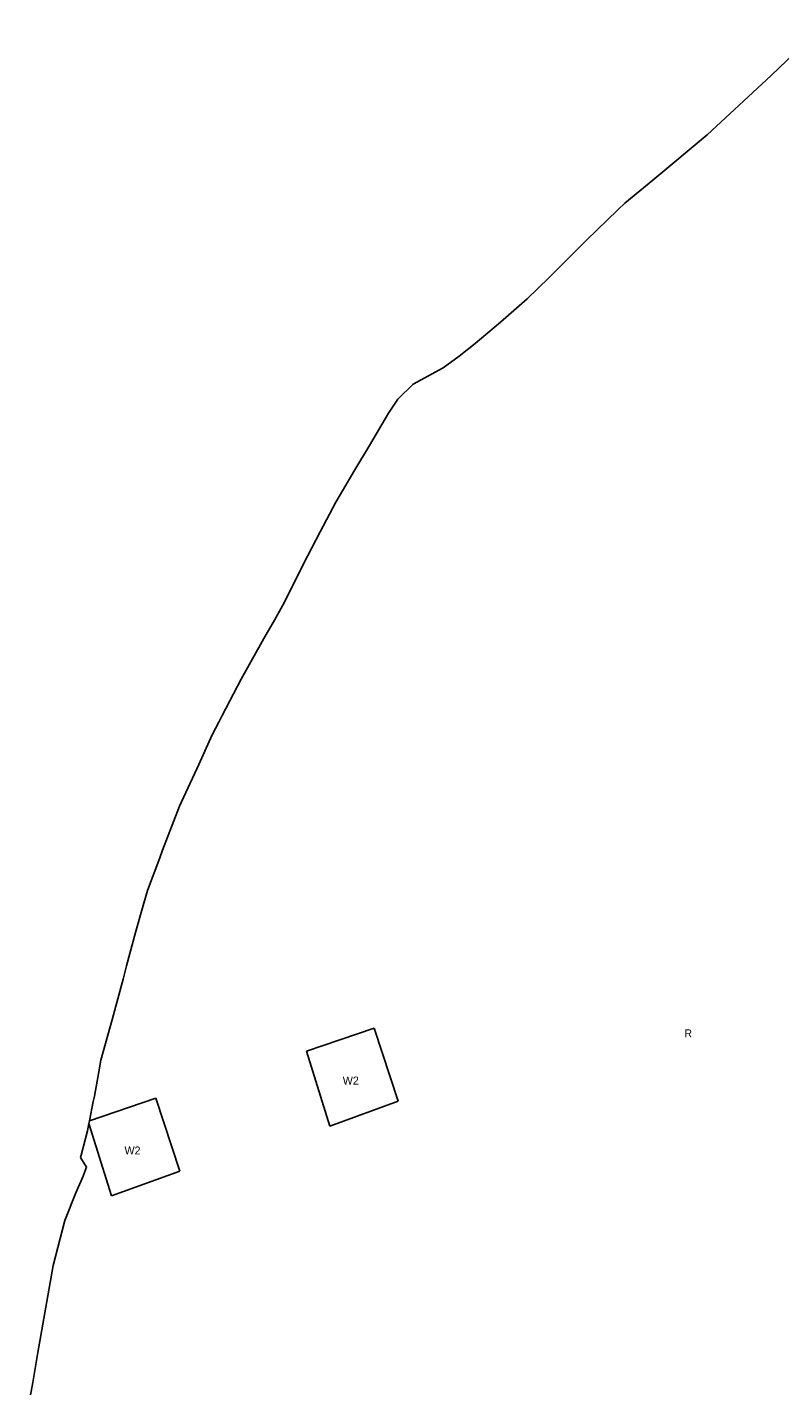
# Model space of a CAD drawing. Extents: x 7435758 to 7439981, y 5550649 to 5554049.
# Drawn here: x 7438745 to 7439233, y 5552845 to 5553728 of the extents above; entities that cross this region are included whole.
import ezdxf

# ---------------------------------------------------------------- set-up
doc = ezdxf.new("R2010")
doc.units = 0
doc.layers.add('linie_rozgraniczające', color=7, linetype='Continuous')
doc.layers.add('oznaczenia_przeznaczen', color=7, linetype='Continuous')

msp = doc.modelspace()

# ---------------------------------------------------------------- linework, layer by layer
at = {"layer": 'linie_rozgraniczające'}
for p, q in [((7439227.86, 5553696.6), (7439260.4, 5553728.02)), ((7439186.11, 5553658.17), (7439227.86, 5553696.6)), ((7439152.26, 5553629.66), (7439186.11, 5553658.17)), ((7439132.68, 5553613.63), (7439152.26, 5553629.66)), ((7439107.81, 5553589.71), (7439128.2, 5553609.32)), ((7439128.2, 5553609.32), (7439132.68, 5553613.63)), ((7439107, 5553588.88), (7439107.81, 5553589.71)), ((7439083.41, 5553565.12), (7439107, 5553588.88)), ((7439069.37, 5553551.52), (7439083.41, 5553565.12)), ((7439052.08, 5553536.34), (7439069.37, 5553551.52)), ((7439035.6, 5553522.58), (7439052.08, 5553536.34)), ((7439025.09, 5553514.22), (7439035.6, 5553522.58)), ((7439014.8, 5553506.77), (7439025.09, 5553514.22)), ((7438995.32, 5553496.09), (7439014.8, 5553506.77)), ((7438985.34, 5553486.36), (7438995.32, 5553496.09)), ((7438979.2, 5553477.3), (7438985.34, 5553486.36)), ((7438966.92, 5553456.33), (7438979.2, 5553477.3)), ((7438957.43, 5553440.36), (7438966.92, 5553456.33)), ((7438945.16, 5553419.54), (7438957.43, 5553440.36)), ((7438934.92, 5553400.1), (7438945.16, 5553419.54)), ((7438924.02, 5553379.4), (7438934.92, 5553400.1)), ((7438911.82, 5553354.58), (7438924.02, 5553379.4)), ((7438905.21, 5553342.9), (7438911.82, 5553354.58)), ((7438898.39, 5553330.86), (7438905.21, 5553342.9)), ((7438883.68, 5553304.39), (7438898.39, 5553330.86)), ((7438871.37, 5553280.9), (7438883.68, 5553304.39)), ((7438869.09, 5553276.56), (7438871.37, 5553280.9)), ((7438864.81, 5553268.4), (7438869.09, 5553276.56)), ((7438856.14, 5553249.03), (7438864.81, 5553268.4)), ((7438843.57, 5553221.94), (7438856.14, 5553249.03)), ((7438832.57, 5553193.37), (7438843.57, 5553221.94)), ((7438830.71, 5553188.34), (7438832.57, 5553193.37)), ((7438822.85, 5553167.13), (7438830.71, 5553188.34)), ((7438819.22, 5553154.39), (7438822.85, 5553167.13)), ((7438815.08, 5553139.82), (7438819.22, 5553154.39)), ((7438809.24, 5553118.23), (7438815.08, 5553139.82)), ((7438806.93, 5553109.65), (7438809.24, 5553118.23)), ((7438800.03, 5553083.99), (7438806.93, 5553109.65)), ((7438792.59, 5553056.9), (7438800.03, 5553083.99)), ((7438969.91, 5553077.82), (7438926.04, 5553062.79)), ((7438985.61, 5553030.26), (7438969.91, 5553077.82)), ((7438926.04, 5553062.79), (7438941.25, 5553014.17)), ((7438791.25, 5553049.46), (7438792.59, 5553056.9)), ((7438788.37, 5553033.58), (7438791.25, 5553049.46)), ((7438787.56, 5553030.15), (7438788.37, 5553033.58)), ((7438828.16, 5553032.39), (7438785.12, 5553017.64)), ((7438785.12, 5553017.64), (7438787.56, 5553030.15)), ((7438843.86, 5552984.84), (7438828.16, 5553032.39)), ((7438941.25, 5553014.17), (7438985.61, 5553030.26)), ((7438783.82, 5553010.96), (7438784.78, 5553015.92)), ((7438784.78, 5553015.92), (7438785.12, 5553017.64)), ((7438784.78, 5553015.92), (7438799.5, 5552968.74)), ((7438779.79, 5552995.33), (7438783.82, 5553010.96)), ((7438779.4, 5552993.83), (7438779.79, 5552995.33)), ((7438783.28, 5552987.53), (7438779.4, 5552993.83)), ((7438776.33, 5552970.83), (7438780.96, 5552981.58)), ((7438780.96, 5552981.58), (7438782.12, 5552984.55)), ((7438782.12, 5552984.55), (7438783.28, 5552987.53)), ((7438799.5, 5552968.74), (7438843.86, 5552984.84)), ((7438769.16, 5552952.73), (7438776.33, 5552970.83)), ((7438761.62, 5552923.64), (7438769.16, 5552952.73)), ((7438756.84, 5552896.6), (7438761.62, 5552923.64)), ((7438751.67, 5552867.14), (7438756.84, 5552896.6)), ((7438748.26, 5552847.53), (7438751.67, 5552867.14)), ((7438744.68, 5552827.83), (7438748.26, 5552847.53))]:
    msp.add_line(p, q, dxfattribs=at)

# ---------------------------------------------------------------- texts
at = {"layer": 'oznaczenia_przeznaczen'}
for s, p in [('R', (7439171.36, 5553071.75)), ('W2', (7438949.58, 5553041.11)), ('W2', (7438807.85, 5552995.69))]:
    msp.add_text(s, height=5.2, dxfattribs=at).set_placement(p)

doc.saveas('drawing.dxf')
